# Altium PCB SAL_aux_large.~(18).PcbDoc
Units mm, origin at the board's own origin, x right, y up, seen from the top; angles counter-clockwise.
Board outline 62 x 80 mm, 2 copper layers (Top Layer, Bottom Layer); 30 components, 47 nets, 146 pads, 9 vias.
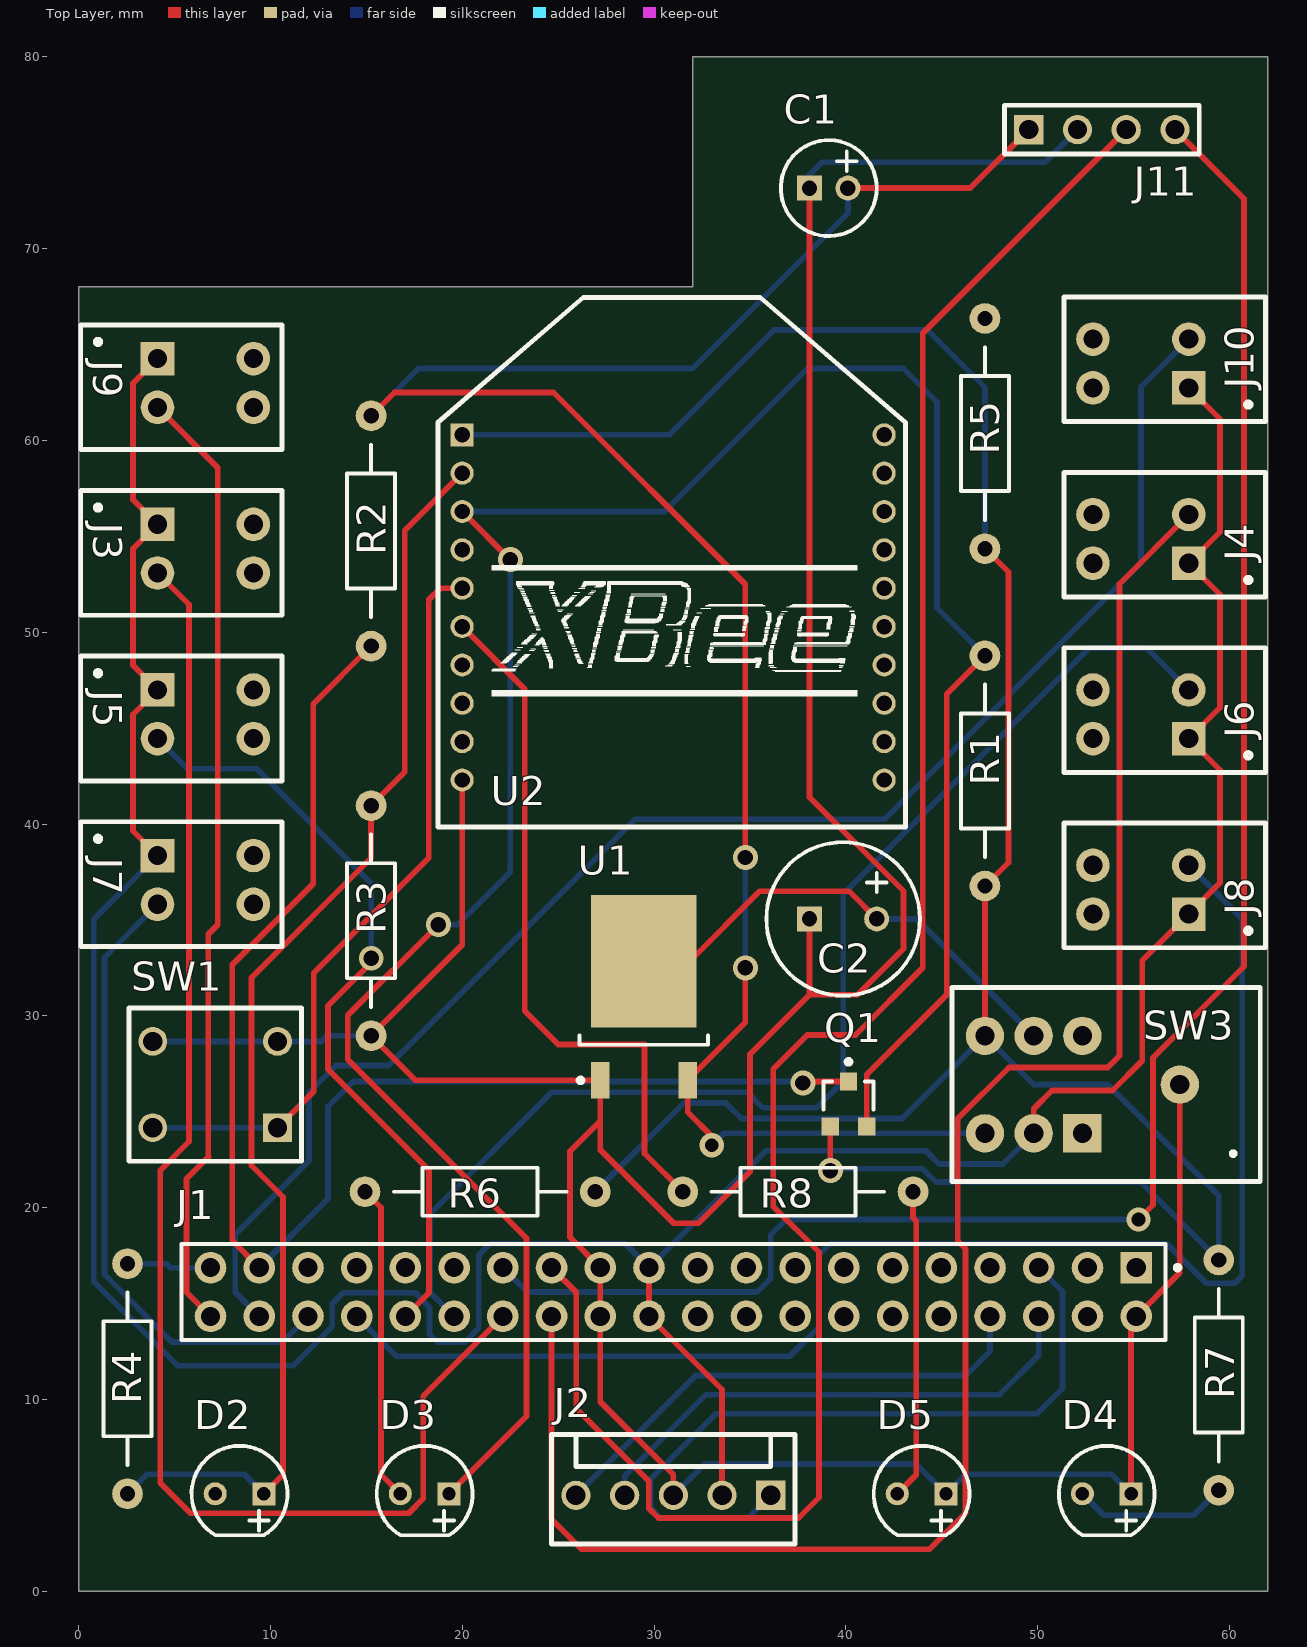
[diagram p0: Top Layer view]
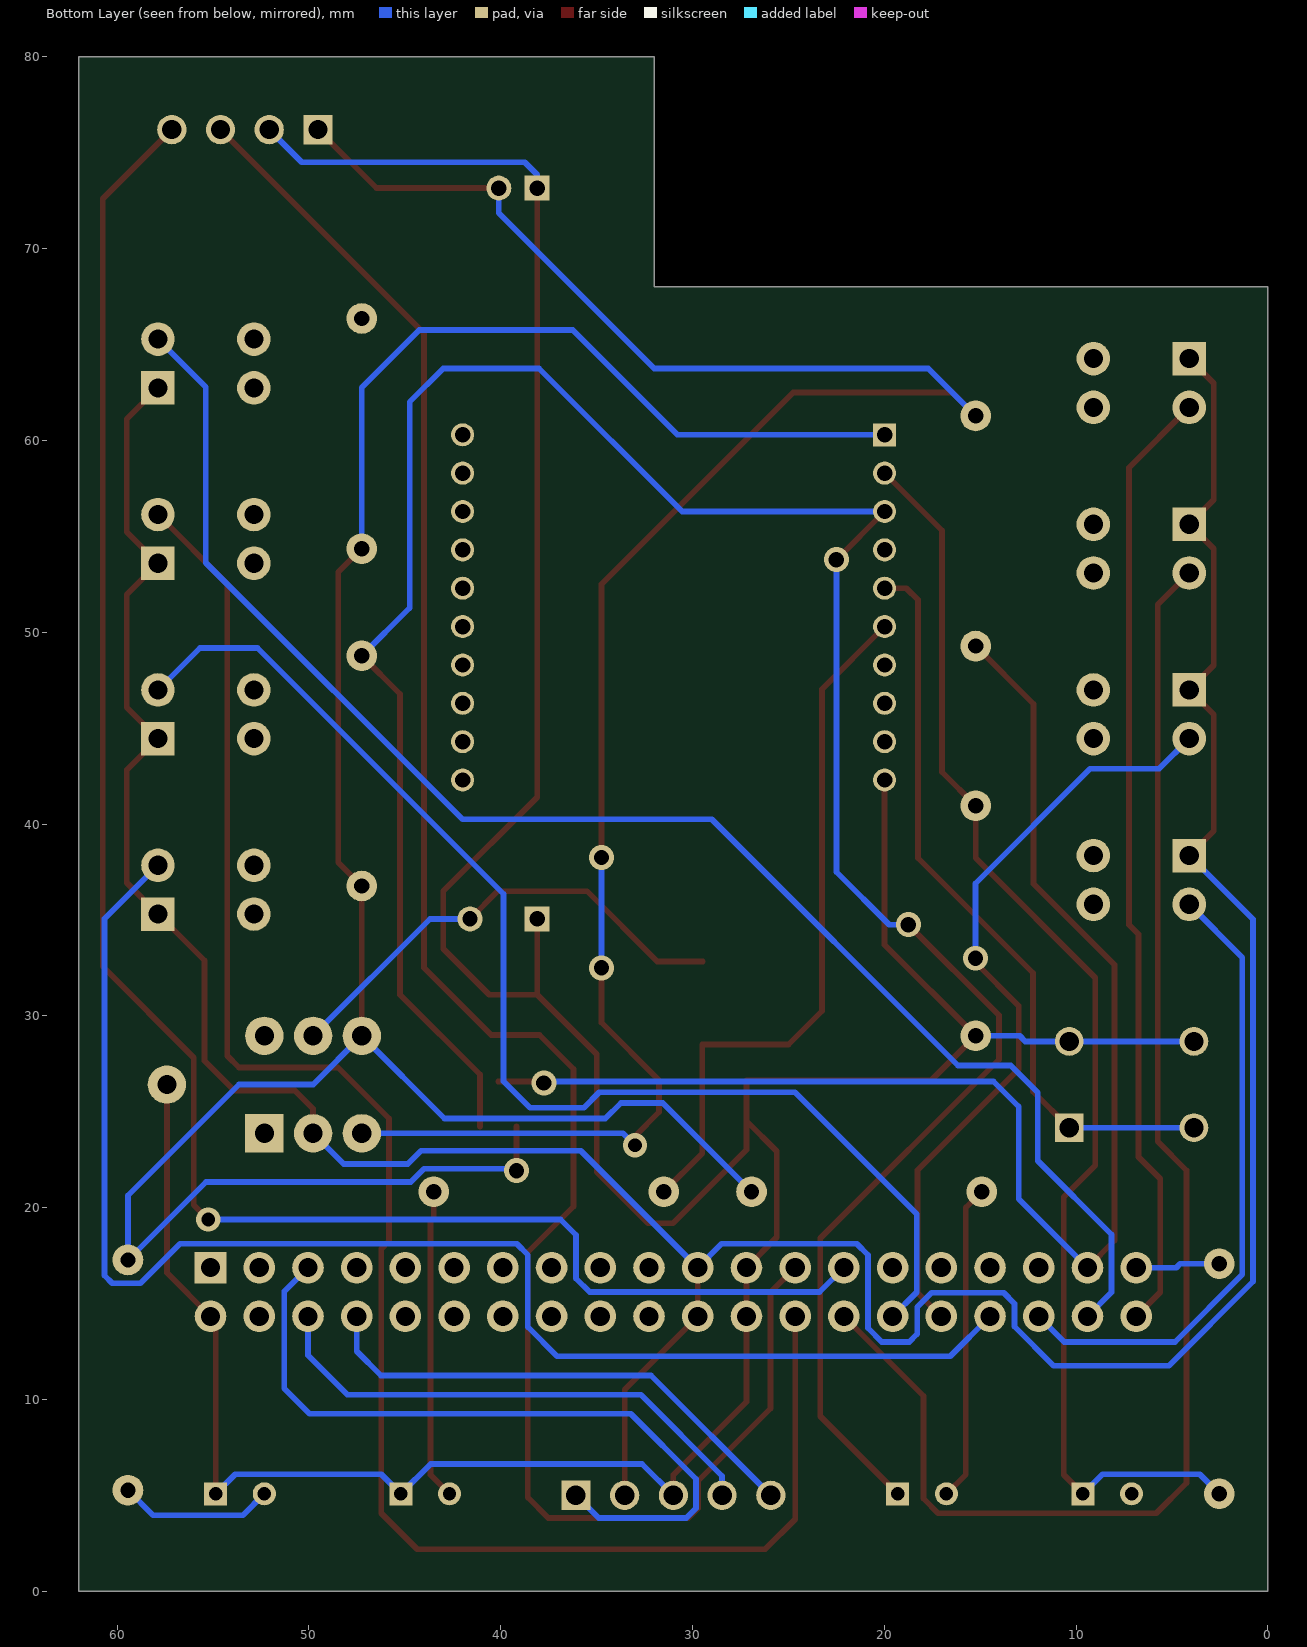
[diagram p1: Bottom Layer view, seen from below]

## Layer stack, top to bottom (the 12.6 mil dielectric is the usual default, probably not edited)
Top Layer: signal copper 0.0356
Dielectric: dielectric 0.32, FR-4, Dk 4.8
Bottom Layer: signal copper 0.0356

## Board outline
0,0 62,0 62,80 32,80 32,68 0,68

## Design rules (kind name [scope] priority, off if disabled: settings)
Clearance [All] p1: gap=0.254
PolygonConnect [All] p1: connectstyle=Relief reliefconductorwidth=0.254 reliefentries=4 polygonreliefangle="90 Angle"
RoomDefinition SAL_aux [InComponentClass('SAL_aux')] p1: confinementstyle=ConfineIn formatcopy=TRUE lockcomponents=FALSE outline 0,0 62,0 62,80 0,80
RoutingVias [All] p1: holewidth=0.711 width=1.27 viastyle="Through Hole" minholewidth=0.711 minwidth=1.27 maxholewidth=0.711 maxwidth=1.27
SilkscreenOverComponentPads [All] p1: minsilkscreentomaskgap=0.254
SolderMaskExpansion [All] p1: expansion=0.102
TestPointUsage [All] p1: valid=0 allowmultiple=FALSE
Testpoint [All] p1: side=15 testpointundercomponent=TRUE minsize=1.016 maxsize=2.54 preferedsize=1.524 minholesize=0 maxholesize=1.016 preferedholesize=0.813 testpointgrid=0.025 style=1023 order=0-112345678
Width [All] p1: maxlimit=1 minlimit=0.254 preferedwidth=0.3 checkconnectedcopper=TRUE
23 further rules are at their usual default settings.

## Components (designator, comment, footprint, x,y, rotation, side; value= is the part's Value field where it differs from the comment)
C1 "10 uF" "PANASONIC ECA1HAM100X" 38.1,73.152 r0 top
C2 "100 uF" "PANASONIC ECA1HAM101X" 38.1,35.052 r0 top
D2 "Yellow" "VISHAY TLLR4401" 7.112,5.08 r0 top
D3 "Red" "VISHAY TLLR4401" 16.764,5.08 r0 top
D4 "Green" "VISHAY TLLR4401" 52.324,5.08 r0 top
D5 "Blue" "VISHAY TLLR4401" 42.672,5.08 r0 top
J1 "SSW-120-01-G-D" "SAMTEC SSW-120-1-G-D" 31,15.6 r180 top
J2 "I2C Connector" "TYCO 640456-5" 31,5 r0 top
J3 "WAGO 234-502" "WAGO 234-502" 6.604,54.356 r270 top
J4 "WAGO 234-502" "WAGO 234-502" 55.372,54.864 r90 top
J5 "WAGO 234-502" "WAGO 234-502" 6.604,45.72 r270 top
J6 "WAGO 234-502" "WAGO 234-502" 55.372,45.72 r90 top
J7 "WAGO 234-502" "WAGO 234-502" 6.604,37.084 r270 top
J8 "WAGO 234-502" "WAGO 234-502" 55.372,36.576 r90 top
J9 "WAGO 234-502" "WAGO 234-502" 6.604,62.992 r270 top
J10 "WAGO 234-502" "WAGO 234-502" 55.372,64.008 r90 top
J11 "TSW-104-07-G-S" "SAMTEC TSW-104-XX-X-S" 53.34,76.2 r0 top
Q1 "BSS138" SOT23 40.132,25.4 r0 top
R1 "10K" Resistência 47.244,48.768 r270 top
R2 "10K" Resistência 15.24,49.276 r90 top
R3 "10K" Resistência 15.24,28.956 r90 top
R4 "10K" Resistência 2.54,5.08 r90 top
R5 "1K" Resistência 47.244,54.356 r90 top
R6 "1K" Resistência 26.924,20.828 r180 top
R7 "1K" Resistência 59.436,17.272 r270 top
R8 "1K" Resistência 31.496,20.828 r0 top
SW1 "OMRON B3F-1002" "OMRON B3F-1002" 7.112,26.416 r0 top
SW3 "MULTICOMP 2AD1T2A2M7RE" "MULTICOMP 2AD1T2A2M7RE" 49.784,26.416 r90 top
U1 "LM1117DT-3.3" TD03B_N 29.464,30.988 r90 top
U2 "XBee" XBee 30.988,50.292 r0 top

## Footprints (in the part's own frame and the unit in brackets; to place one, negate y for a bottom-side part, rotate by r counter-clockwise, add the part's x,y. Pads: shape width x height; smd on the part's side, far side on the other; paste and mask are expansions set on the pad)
"MULTICOMP 2AD1T2A2M7RE" [mm] "Switch, DPDT ON-ON"
  rect 2x2 hole 1: 1(-2.54,-2.54)
  round 2 hole 1: 2(-2.54,0) 3(-2.54,2.54) 4(2.54,-2.54) 5(2.54,0) 6(2.54,2.54) GND(0,-7.62)
  silkscreen extent -5.06,-11.81 5.05,4.25
"OMRON B3F-1002" [mm] "6.0mm Tactil Switch"
  rect 1.5x1.5 hole 1: 1(3.25,-2.25)
  round 1.5 hole 1: 2(-3.25,-2.25) 3(3.25,2.25) 4(-3.25,2.25)
  silkscreen extent -4.5,-4 4.5,4
"PANASONIC ECA1HAM100X" [mm]
  rect 1.3x1.3 hole 0.8: 1(0,0)
  round 1.3 hole 0.8: 2(2,0)
  silkscreen extent -1.5,-2.5 3.5,2.5
"PANASONIC ECA1HAM101X" [mm]
  rect 1.3x1.3 hole 0.8: 1(0,0)
  round 1.3 hole 0.8: 2(3.5,0)
  silkscreen extent -2.25,-4 5.75,4
Resistência [mm]
  round 1.6 hole 0.8: 1(0,0) 2(12,0)
  silkscreen extent 1.5,-1.25 10.5,1.25
"SAMTEC SSW-120-1-G-D" [mm]
  rect 1.65x1.65 / inner round 1.65 / far side rect 1.65x1.65 hole 1 mask+0: 1(-24.13,-1.27)
  round 1.65 hole 1 mask+0: 2(-24.13,1.27) 3(-21.59,-1.27) 4(-21.59,1.27) 5(-19.05,-1.27) 6(-19.05,1.27) 7(-16.51,-1.27) 8(-16.51,1.27) 9(-13.97,-1.27) 10(-13.97,1.27) 11(-11.43,-1.27) 12(-11.43,1.27) 13(-8.89,-1.27) 14(-8.89,1.27) 15(-6.35,-1.27) 16(-6.35,1.27) 17(-3.81,-1.27) 18(-3.81,1.27) 19(-1.27,-1.27) 20(-1.27,1.27) 21(1.27,-1.27) 22(1.27,1.27) 23(3.81,-1.27) 24(3.81,1.27) 25(6.35,-1.27) 26(6.35,1.27) 27(8.89,-1.27) 28(8.89,1.27) 29(11.43,-1.27) 30(11.43,1.27) 31(13.97,-1.27) 32(13.97,1.27) 33(16.51,-1.27) 34(16.51,1.27) 35(19.05,-1.27) 36(19.05,1.27) 37(21.59,-1.27) 38(21.59,1.27) 39(24.13,-1.27) 40(24.13,1.27)
  silkscreen extent -26.41,-2.5 25.65,2.5
"SAMTEC TSW-104-XX-X-S" [mil] "4 pin 2.54mm pitch header"
  rect 60x60 hole 39.37: 1(-150,0)
  round 60 hole 39.37: 2(-50,0) 3(50,0) 4(150,0)
  silkscreen extent -200,-50 200,50
SOT23 [mm] "SOT-23; 3 Leads; Body 3.1 x 2.5 mm, inc. leads (LxW max), Alternate Lead Configuration"
  rect 0.9x0.95 smd: 1(0,1.175) 2(0.95,-1.175) 3(-0.95,-1.175)
  silkscreen extent -1.3,-0.3 1.3,2.32
TD03B_N [mm] "D-PAK, 4-Leads, Body 6.1x6.6mm, Pitch 2.29mm, Lead Span 9.7mm, IPC Medium Density"
  rect 1.9x0.95 smd: 1(-4.35,2.28) 3(-4.35,-2.28)
  rect 6.9x5.5 smd: 4(1.85,0)
  silkscreen extent -4.47,-3.35 -2,3.43
"TYCO 640456-5" [mil] "I2C Connector"
  rect 60x60 hole 40.16: 1(200,0)
  round 60 hole 40.16: 2(100,0) 3(0,0) 4(-100,0) 5(-200,0)
  silkscreen extent -250,-100 250,125
"VISHAY TLLR4401" [mm] "3mm LED"
  round 1.2 hole 0.7: 1(0,0)
  rect 1.2x1.2 hole 0.7: 2(2.54,0)
  silkscreen extent -1.23,-2.17 3.77,2.5
"WAGO 234-502" [mm]
  rect 1.75x1.75 hole 1: 1(-1.27,-2.5)
  round 1.75 hole 1: 2(-1.27,2.5) 3(1.27,-2.5) 4(1.27,2.5)
  silkscreen extent -3.03,-6.5 3.47,4
XBee [mm] "ZigBee device"
  rect 1.2x1.2 hole 0.8: 1(-11,10)
  round 1.2 hole 0.8: 2(-11,8) 3(-11,6) 4(-11,4) 5(-11,2) 6(-11,0) 7(-11,-2) 8(-11,-4) 9(-11,-6) 10(-11,-8) 11(11,-8) 12(11,-6) 13(11,-4) 14(11,-2) 15(11,0) 16(11,2) 17(11,4) 18(11,6) 19(11,8) 20(11,10)
  silkscreen extent -12.26,-10.44 12.12,17.17

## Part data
C1: library part "PANASONIC ECA1HAM100X"
C2: library part "PANASONIC ECA1HAM101X"
D2 D3 D4 D5: library part "VISHAY TLLG4401", "Green LED PCB 3mm"
J1: library part "SAMTEC SSW-120-01-G-D"
J2: library part "TYCO 640456-5"
J11: library part "SAMTEC TSW-104-07-G-S", "4 pin 2.54mm pitch header"
Q1: "N-Channel Enhancement Mode Vertical DMOS FET"
R1 R2 R3 R4 R5 R6 R7 R8: library part Resistência
SW1: "6.0mm Tact Switch"
U1: "800mA Low-Dropout Linear Regulator"

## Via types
v1: diameter 1.3, hole 0.8, Top Layer to Bottom Layer, 7 vias
v2: diameter 1.27, hole 0.711, Top Layer to Bottom Layer, 2 vias

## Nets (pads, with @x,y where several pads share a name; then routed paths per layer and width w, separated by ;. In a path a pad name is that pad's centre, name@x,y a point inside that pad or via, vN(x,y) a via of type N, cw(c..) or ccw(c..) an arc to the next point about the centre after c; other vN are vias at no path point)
3.3V: Q1.3 R1.2 R5.1 R6.1 R7.1 SW3.6 U2.1 | length 133.5
  Top Layer w0.3: v1(39.182,21.924) Q1.3 ; SW3.6 R1.2 48.466,37.99 48.466,53.134 R5.1
  Bottom Layer w0.3: U2.1 30.792,60.292 36.25,65.75 44.25,65.75 47.244,62.756 R5.1 ; R6.1 31.553,25.457 33.732,25.457 34.547,24.642 42.93,24.642 SW3.6 49.78,26.42 53.648,26.42 59.436,20.632 R7.1 55.368,21.34 44.687,21.34 43.995,22.032 39.29,22.032 v1(39.182,21.924)
"3.3V OUT": C2.2 SW3.5 U1.4 | length 25
  Top Layer w0.3: U1.4 31.838,32.838 35.5,36.5 40.152,36.5 C2.2
  Bottom Layer w0.3: C2.2 43.688,35.052 SW3.5
/INT: J1.20
/RESET: J1.5 J2.1 | length 38.7
  Bottom Layer w0.3: J2.1 34.894,3.814 30.331,3.814 29.823,4.322 29.823,5.846 33.226,9.25 49.965,9.25 51.286,10.57 51.286,15.634 J1.5
A0: J1.7
A4/LSDA: J1.1
A5/LSCL: J1.3
B5: J1.10
C0: J1.25 J11.3 | length 105.6
  Top Layer w0.3: J1.25 25.937,15.583 25.937,9.529 29.721,5.744 29.721,4.322 30.229,3.814 37.519,3.814 38.586,4.881 38.586,17.682 36.211,20.057 36.211,27.233 37.978,29 40.5,29 44,32.5 44,65.59 J11.3
C1: J1.27 J11.4 | length 97.1
  Top Layer w0.3: v2(55.248,19.384) 56,20.136 56,27.817 60.75,32.567 60.75,72.6 J11.4
  Bottom Layer w0.3: J1.27 23.38,15.6 35.36,15.6 36.071,16.311 36.071,18.571 36.884,19.384 v2(55.248,19.384)
C2: J1.29
C5: J1.35
D0: J1.40 J9.3 | length 49.9
  Top Layer w0.3: J9.3 7.25,58.576 7.25,34.75 6.75,34.25 6.75,22.668 6.768,22.651 5.617,21.5 5.617,15.583 J1.40
D1: J1.38 J10.3 | length 81.3
  Bottom Layer w0.3: J1.38 8.157,15.583 8.157,18.597 12,22.44 12,25.996 13.414,27.411 16.161,27.411 29,40.25 42,40.25 55.375,53.625 55.375,62.781 J10.3
D2: J1.36 J7.3 | length 33.1
  Bottom Layer w0.3: J7.3 1.336,33.046 1.336,16.514 4.85,13 10.62,13 J1.36
D3: J1.34 J8.3 | length 75.2
  Bottom Layer w0.3: J1.34 16.57,12.25 37.065,12.25 38.586,13.771 38.586,17.53 39.17,18.114 56.721,18.114 58.779,16.057 60.252,16.057 60.658,16.463 60.658,35.06 J8.3
D4: J1.32 J5.3 | length 41.1
  Top Layer w0.3: v1(15.25,33) 15.25,32.777 13,30.527 13,27.215 18.266,21.95 18.266,15.566 J1.32
  Bottom Layer w0.3: J5.3 5.675,42.879 9.274,42.879 15.25,36.903 15.25,33.446 14.804,33 v1(15.25,33)
D5: J1.30 J6.3 | length 64.9
  Bottom Layer w0.3: J1.30 18.317,15.583 18.317,19.664 24.664,26.011 34.861,26.011 35.671,25.201 38.466,25.201 39.856,26.59 39.856,36.356 52.678,49.178 55.684,49.178 J6.3
D6: J1.28 J3.3 | length 74.6
  Top Layer w0.3: J3.3 5.75,51.44 5.75,23.442 4.25,21.942 4.25,5.638 5.82,4.068 17.199,4.068 17.961,4.83 17.961,10.181 J1.28
D7: J1.26 J4.3 | length 93.8
  Top Layer w0.3: J1.26 24.65,3.754 26.216,2.188 44.352,2.188 46.231,4.068 46.231,17.86 45.825,18.267 45.825,24.642 48.492,27.309 53.648,27.309 54.258,27.919 54.258,52.52 J4.3
DIN: D3.2 Q1.2 R1.1 U2.3 | length 131.8
  Top Layer w0.3: v1(18.75,34.75) 14.024,30.024 14.024,27.726 23.346,18.404 23.346,9.122 D3.2 ; U2.3 v1(22.5,53.78) ; Q1.2 41.082,26.935 45.25,31.103 45.25,46.774 R1.1
  Bottom Layer w0.3: v1(18.75,34.75) 19.75,34.75 22.5,37.5 ; U2.3 30.542,56.292 38,63.75 43,63.75 44.75,62 44.75,51.262 R1.1 ; 22.5,37.53 v1(22.5,53.78)
DOUT: D2.2 R3.2 R4.1 U2.2 | length 66.8
  Top Layer w0.3: D2.2 10.646,6.074 10.646,20.553 9,22.198 9,31.988 15.24,38.228 R3.2 17,42.716 17,55.304 U2.2
  Bottom Layer w0.3: R4.1 3.56,6.1 8.632,6.1 D2.2
EYEB: J1.19
EYEF: J1.9
EYEL: J1.13
EYER: J1.11
NetD3_1: D3.1 R6.2 | length 16.5
  Top Layer w0.3: R6.2 15.751,20.001 15.751,6.093 D3.1
NetD4_1: D4.1 R7.2 | length 8.1
  Bottom Layer w0.3: D4.1 53.438,3.966 58.13,3.966 R7.2
NetD5_1: D5.1 R8.2 | length 16.2
  Top Layer w0.3: D5.1 43.666,6.074 43.666,19.308 43.496,19.478 R8.2
PWM1/SERVOR: J1.18
PWM2/SERVOL: J1.16
PWM3: J1.14
PWM4: J1.12
RESET: SW1.1 SW1.2 U2.5 | length 39.3
  Top Layer w0.3: SW1.1 12.25,26.054 12.25,32.227 18.25,38.227 18.25,51.689 18.853,52.292 U2.5
  Bottom Layer w0.3: SW1.2 SW1.1
RSSI: R8.1 U2.6 | length 36.9
  Top Layer w0.3: U2.6 23.25,47.03 23.25,30.251 25.001,28.5 29.5,28.5 29.5,22.824 R8.1
RX: J1.39 R4.2 | length 4.4
  Bottom Layer w0.3: R4.2 4.575,17.08 4.785,16.87 J1.39
SCL: J1.31
SDA: J1.33
TX: J1.37 Q1.1 R2.1 | length 73.6
  Top Layer w0.3: J1.37 8,18.28 8,32.664 12.221,36.885 12.221,46.257 R2.1 ; v1(37.75,26.5) 37.75,26.55 37.775,26.575 Q1.1
  Bottom Layer w0.3: J1.37 13,20.46 13,25.269 14.306,26.575 37.675,26.575 v1(37.75,26.5)
US_B: J1.17
US_F: J1.15
V+: J1.4
VDD: J1.21 J1.22 J2.2 J3.1 J4.1 J5.1 J6.1 J7.1 J8.1 J9.1 J10.1 SW3.2 | length 177.5
  Top Layer w0.3: J7.1 2.823,39.635 2.823,45.709 J5.1 2.823,48.271 2.823,54.345 J3.1 2.823,56.907 2.823,62.981 J9.1 ; J1.21 J1.22 33.54,10.52 J2.2 ; SW3.2 49.784,25.15 50.74,26.106 53.893,26.106 55.446,27.659 55.446,32.88 J8.1 59.5,36.934 59.5,42.822 J6.1 59.5,46.078 59.5,51.966 J4.1 59.5,55.222 59.5,61.11 J10.1
  Bottom Layer w0.3: J7.1 0.782,35.032 0.782,16.142 5.174,11.75 11.165,11.75 13.211,13.796 13.211,14.99 13.78,15.559 17.539,15.559 18.291,14.807 18.291,13.406 18.697,13 20.137,13 20.857,13.72 20.857,17.53 21.441,18.114 28.486,18.114 J1.21 35.826,22.966 44.163,22.966 44.849,22.28 48.188,22.28 SW3.2
"VDD OUT": C1.2 J11.1 R2.2 SW3.3 U1.3 | length 112.2
  Top Layer w0.3: R2.2 16.464,62.5 24.75,62.5 34.75,52.5 v1(34.75,38.25) ; v2(33,23.25) 33,23.725 31.744,24.981 U1.3 34.75,29.644 v1(34.75,32.5) v1@34.75,32.75 ; C1.2 46.482,73.152 J11.1
  Bottom Layer w0.3: R2.2 17.714,63.75 32,63.75 40.1,71.85 C1.2 ; v2(33,23.25) 33.626,23.876 SW3.3 ; v1(34.75,32.5) 34.75,38.75 v1(34.75,38.25)
VSS: C1.1 C2.1 D4.2 D5.2 J1.2 J1.23 J1.24 J2.3 J11.2 R3.1 SW1.3 SW1.4 SW3.GND U1.1 U2.10 | length 202.4
  Top Layer w0.3: U2.10 19.988,33.704 R3.1 17.558,26.638 U1.1 27.184,24.518 ; J2.3 31,6.068 27.19,9.878 J1.24 J1.23 25.606,18.454 25.606,22.94 27.184,24.518 ; C2.1 38.1,31.1 ; C1.1 38.1,41.4 43,36.5 43,33.5 40.6,31.1 38.1,31.1 ; D4.2 54.864,14.064 J1.2 57.404,16.604 SW3.GND ; 27.184,24.518 27.184,23.016 31.019,19.181 32.312,19.181 35,21.869 35,28 38.1,31.1
  Bottom Layer w0.3: SW1.4 SW1.3 12.652,28.666 12.942,28.956 R3.1 ; J2.3 32.638,6.638 43.654,6.638 D5.2 46.232,6.1 53.844,6.1 D4.2 ; C1.1 38.1,73.85 38.75,74.5 50.37,74.5 J11.2
XAXIS: J1.8 J2.5 | length 26.5
  Bottom Layer w0.3: J2.5 32.17,11.25 46.25,11.25 47.51,12.51 J1.8
YAXIS: J1.6 J2.4 | length 27.2
  Bottom Layer w0.3: J2.4 28.46,6.004 32.706,10.25 48,10.25 50.05,12.3 J1.6
pads on no net: D2.1 J3.2 J3.4 J4.2 J4.4 J5.2 J5.4 J6.2 J6.4 J7.2 J7.4 J8.2 J8.4 J9.2 J9.4 J10.2 J10.4 R5.2 SW3.1 SW3.4 U2.4 U2.7 U2.8 U2.9 U2.11 U2.12 U2.13 U2.14 U2.15 U2.16 U2.17 U2.18 U2.19 U2.20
